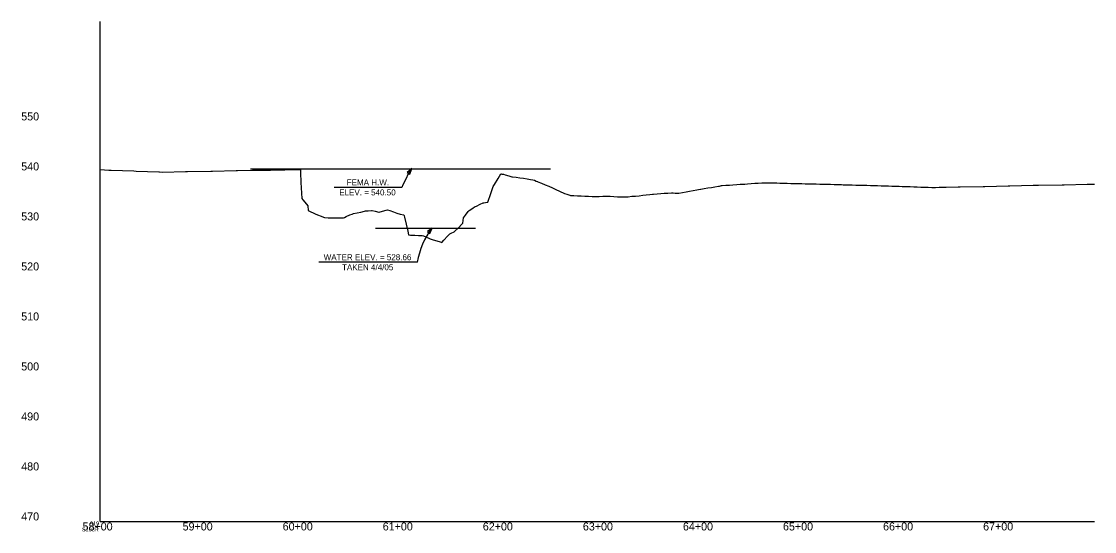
# Model space of a CAD drawing. Extents: x 1961504 to 1964196, y 1107046 to 1115093.
# Drawn here: x 1961505 to 1962577, y 1113082 to 1113593 of the extents above; entities that cross this region are included whole.
import ezdxf

# ---------------------------------------------------------------- set-up
doc = ezdxf.new("R2010")
doc.units = 0
for name, color, linetype in [('Level 40', 7, 'Continuous'), ('Level 41', 7, 'Continuous'), ('Level 42', 7, 'Continuous'), ('Level 63', 7, 'Continuous')]:
    doc.layers.add(name, color=color, linetype=linetype)

msp = doc.modelspace()

# ---------------------------------------------------------------- linework, layer by layer
at = {"layer": 'Level 40'}
for points in [[(1961583.7, 1113444.4), (1961592.3, 1113444), (1961594.7, 1113444), (1961617.3, 1113443.1), (1961619.7, 1113443), (1961642.3, 1113442.2), (1961642.8, 1113442.1), (1961645.9, 1113442), (1961668.8, 1113442.4), (1961670.9, 1113442.5), (1961694.1, 1113442.9), (1961695.9, 1113443), (1961719.5, 1113443.4), (1961720.9, 1113443.4), (1961735.7, 1113443.7), (1961739.3, 1113443.8), (1961742.9, 1113443.8), (1961744.8, 1113443.9), (1961745.9, 1113443.9), (1961745.9, 1113443.9), (1961746.5, 1113443.9), (1961748.4, 1113443.9), (1961749.5, 1113444), (1961750.2, 1113444), (1961753.8, 1113444), (1961757.4, 1113444.1), (1961761, 1113444.2), (1961764.6, 1113444.3), (1961768.2, 1113444.3), (1961771.8, 1113444.4), (1961773.4, 1113444.4), (1961774.2, 1113444.5), (1961775.4, 1113444.5), (1961779.1, 1113444.6), (1961782.7, 1113444.6), (1961783.7, 1113444.6), (1961783.8, 1113444.7), (1961783.9, 1113441.5), (1961784.2, 1113431.5), (1961785.3, 1113415.4), (1961786.3, 1113414.3), (1961789.9, 1113409.8), (1961791.2, 1113408.1), (1961791.5, 1113403.4), (1961793.5, 1113402.4), (1961797.1, 1113400.8), (1961798.5, 1113400.1), (1961800.7, 1113399.2), (1961804.3, 1113397.8), (1961806.9, 1113396.7), (1961807.9, 1113396.4), (1961808, 1113396.4), (1961811.6, 1113396.3), (1961815.2, 1113396.3), (1961818.8, 1113396.3), (1961822.4, 1113396.3), (1961826, 1113396.2), (1961826.8, 1113396.2), (1961827.9, 1113396.6), (1961829.6, 1113397.4), (1961833.2, 1113399.1), (1961835.4, 1113400), (1961836.8, 1113400.4), (1961840.4, 1113401.2), (1961844.1, 1113402), (1961847.7, 1113402.9), (1961848.7, 1113403.1), (1961851.3, 1113403.3), (1961854.9, 1113403.6), (1961855.4, 1113403.6), (1961858.5, 1113402.8), (1961862.1, 1113401.9), (1961862.3, 1113401.9), (1961865.7, 1113402.8), (1961869.3, 1113403.9), (1961870.6, 1113404.2), (1961873, 1113403.4), (1961876.6, 1113402.1), (1961880.2, 1113400.9), (1961883.4, 1113399.7), (1961883.8, 1113399.7), (1961886.7, 1113399.2), (1961887.3, 1113398.5), (1961887.4, 1113398.3), (1961887.8, 1113396.9), (1961891, 1113382.7), (1961891.8, 1113379.2), (1961893.7, 1113378.9), (1961894.6, 1113378.9), (1961898.2, 1113378.7), (1961901.8, 1113378.6), (1961905.5, 1113378.4), (1961906.8, 1113378.3), (1961909.1, 1113377.2), (1961912.7, 1113375.5), (1961913.4, 1113375.1), (1961916.3, 1113374.2), (1961919.9, 1113373.2), (1961923.5, 1113372.1), (1961925.1, 1113371.6), (1961927.1, 1113373.8)], [(1961927.1, 1113373.8), (1961930.7, 1113377.9), (1961932.9, 1113380.3), (1961934.3, 1113380.9), (1961937.5, 1113382.3), (1961938, 1113382.7), (1961941.6, 1113386.3), (1961945.2, 1113389.9), (1961946.1, 1113390.8), (1961946.8, 1113396.1), (1961948.8, 1113398.9), (1961951.3, 1113402.6), (1961952.4, 1113403.4), (1961956, 1113405.9), (1961957.8, 1113407.2), (1961959.6, 1113408), (1961963.2, 1113409.7), (1961966.4, 1113411.2), (1961966.9, 1113411.2), (1961967, 1113411.2), (1961970.5, 1113411.7), (1961971.1, 1113411.8), (1961974.1, 1113420.5), (1961976.5, 1113427.5), (1961977.7, 1113429.5), (1961981.3, 1113435.6), (1961984, 1113440.1), (1961984.3, 1113440.1), (1961984.9, 1113440), (1961986.7, 1113439.8), (1961988.5, 1113439.3), (1961992.1, 1113438.2), (1961995.1, 1113437.3), (1961995.7, 1113437.2), (1961999.4, 1113436.7), (1962003, 1113436.2), (1962006.6, 1113435.7), (1962010.2, 1113435.2), (1962013.8, 1113434.6), (1962016.1, 1113434.3), (1962017.4, 1113433.8), (1962017.4, 1113433.7), (1962017.5, 1113433.7), (1962019.3, 1113433), (1962020.7, 1113432.5), (1962021, 1113432.3), (1962024.6, 1113430.8), (1962028.2, 1113429.3), (1962031.9, 1113427.7), (1962035.5, 1113426.1), (1962039.1, 1113424.5), (1962042.7, 1113422.8), (1962044, 1113422.2), (1962046.3, 1113421.2), (1962047.8, 1113420.5), (1962049.9, 1113419.7), (1962053, 1113418.7), (1962053.5, 1113418.6), (1962057.1, 1113418.4), (1962060.7, 1113418.2), (1962060.7, 1113418.2), (1962064.4, 1113418.1), (1962068, 1113418), (1962068, 1113418), (1962071.6, 1113417.8), (1962075.2, 1113417.6), (1962078.8, 1113417.4), (1962078.9, 1113417.4), (1962082.4, 1113417.5), (1962086, 1113417.7), (1962089.6, 1113417.8), (1962093, 1113417.9), (1962093.3, 1113417.8), (1962096.9, 1113417.5), (1962100.5, 1113417.2), (1962100.6, 1113417.2), (1962104.1, 1113417.2), (1962107.7, 1113417.2), (1962110.5, 1113417.2), (1962111.3, 1113417.3), (1962114.9, 1113417.7), (1962118.5, 1113418), (1962122.1, 1113418.3), (1962122.3, 1113418.3), (1962125.8, 1113418.7), (1962129.4, 1113419.2), (1962133, 1113419.5), (1962135.5, 1113419.8), (1962136.6, 1113419.9), (1962140.2, 1113420.3), (1962143.8, 1113420.6), (1962143.8, 1113420.6), (1962147.4, 1113420.8), (1962151, 1113421), (1962154.6, 1113421.1), (1962156.2, 1113421.1), (1962158.3, 1113421), (1962161.6, 1113420.7), (1962161.9, 1113420.8), (1962165.5, 1113421.5), (1962169.1, 1113422.2)], [(1962169.1, 1113422.2), (1962172.7, 1113422.9), (1962176.3, 1113423.5), (1962179.9, 1113424.2), (1962181.5, 1113424.4), (1962183.5, 1113424.9), (1962184, 1113425), (1962187.2, 1113425.5), (1962190.8, 1113426.1), (1962194.4, 1113426.6), (1962198, 1113427.1), (1962201.6, 1113427.7), (1962202.6, 1113427.8), (1962204.4, 1113428.4), (1962205.2, 1113428.4), (1962208.8, 1113428.7), (1962212.4, 1113429), (1962216, 1113429.2), (1962219.7, 1113429.4), (1962223.3, 1113429.7), (1962226.9, 1113429.9), (1962227.7, 1113430), (1962230.5, 1113430.2), (1962234.1, 1113430.4), (1962237.7, 1113430.7), (1962241.3, 1113430.9), (1962244.9, 1113431.1), (1962245.7, 1113431.2), (1962248.5, 1113431.2), (1962251.5, 1113431.2), (1962252.2, 1113431.2), (1962252.9, 1113431.2), (1962253.1, 1113431.1), (1962255.8, 1113431.1), (1962256.6, 1113431.1), (1962259.4, 1113431.1), (1962259.9, 1113431.1), (1962263, 1113431), (1962266.6, 1113430.9), (1962270.2, 1113430.8), (1962273.8, 1113430.6), (1962277.4, 1113430.5), (1962281, 1113430.4), (1962281.7, 1113430.4), (1962284.7, 1113430.4), (1962288.3, 1113430.3), (1962291.9, 1113430.3), (1962291.9, 1113430.3), (1962295.5, 1113430.2), (1962299.1, 1113430.1), (1962302.7, 1113429.9), (1962306.3, 1113429.8), (1962306.7, 1113429.8), (1962308.5, 1113429.8), (1962309.9, 1113429.8), (1962310.1, 1113429.8), (1962313.6, 1113429.7), (1962317.2, 1113429.6), (1962320.8, 1113429.5), (1962324.4, 1113429.4), (1962326.1, 1113429.3), (1962328, 1113429.3), (1962331.6, 1113429.2), (1962335.2, 1113429.1), (1962335.2, 1113429.1), (1962338.8, 1113429), (1962342.4, 1113428.9), (1962346.1, 1113428.8), (1962349.7, 1113428.7), (1962353.3, 1113428.6), (1962354.7, 1113428.6), (1962356.9, 1113428.5), (1962360.2, 1113428.4), (1962360.5, 1113428.4), (1962364.1, 1113428.3), (1962367.7, 1113428.2), (1962371.3, 1113428.1), (1962374.9, 1113428), (1962378.6, 1113427.8), (1962381.8, 1113427.7), (1962382.2, 1113427.7), (1962385.2, 1113427.6), (1962385.8, 1113427.6), (1962389.4, 1113427.5), (1962393, 1113427.4), (1962396.6, 1113427.2), (1962400.2, 1113427.1), (1962403.8, 1113427), (1962407.5, 1113426.9), (1962407.7, 1113426.9), (1962410.2, 1113426.8), (1962410.6, 1113426.8), (1962411.1, 1113426.7), (1962414.7, 1113426.6), (1962416, 1113426.6), (1962418.3, 1113426.6), (1962418.4, 1113426.6), (1962421.9, 1113426.7), (1962425.5, 1113426.8), (1962429.1, 1113426.8), (1962441, 1113427.1)], [(1962441, 1113427.1), (1962443.1, 1113427.1), (1962466, 1113427.6), (1962467.8, 1113427.6), (1962491, 1113428.1), (1962492.6, 1113428.2), (1962516, 1113428.7), (1962516.2, 1113428.7), (1962520, 1113428.7), (1962521.3, 1113428.8), (1962545, 1113429.3), (1962547, 1113429.3), (1962570, 1113429.8), (1962572.6, 1113429.8), (1962577.3, 1113429.9)]]:
    msp.add_lwpolyline(points, dxfattribs=at)
at = {"layer": 'Level 41'}
for p, q in [((1961733.7, 1113445.1), (1962033.7, 1113445.1)), ((1961885.2, 1113426.6), (1961817.5, 1113426.6)), ((1961858.7, 1113385.9), (1961958.7, 1113385.9)), ((1961900.6, 1113351.8), (1961802, 1113351.8))]:
    msp.add_line(p, q, dxfattribs=at)
for points in [[(1961893.1, 1113439.8), (1961894.9, 1113445.6), (1961890.5, 1113441.5)], [(1961913.1, 1113380.5), (1961915.4, 1113386), (1961910.6, 1113382.4)]]:
    msp.add_lwpolyline(points, close=True, dxfattribs=at)
for centre, radius, start, end in [((1961987.7, 1113386.1), 110.2, 147.3254, 158.4252), ((1961975.9, 1113339.7), 76.3, 142.5817, 170.8964)]:
    msp.add_arc(centre, radius, start, end, dxfattribs=at)
at = {"layer": 'Level 63'}
for q in [(1961583.7, 1113592.6), (1962577.3, 1113092.6), (1961583.7, 1113092.6)]:
    msp.add_line((1961583.7, 1113092.6), q, dxfattribs=at)

# ---------------------------------------------------------------- texts
at = {"layer": 'Level 41'}
for s, p in [('FEMA H.W.', (1961830, 1113428.6)), ('ELEV. = 540.50', (1961822.5, 1113418.6)), ('WATER ELEV. = 528.66', (1961807, 1113353.8)), ('TAKEN 4/4/05', (1961825.3, 1113343.8))]:
    msp.add_text(s, height=6, dxfattribs=at).set_placement(p)
at = {"layer": 'Level 42'}
for s, p in [('550', (1961504.7, 1113493.6)), ('540', (1961504.7, 1113443.6)), ('530', (1961504.7, 1113393.6)), ('520', (1961504.7, 1113343.6)), ('510', (1961504.7, 1113293.6)), ('500', (1961504.7, 1113243.6)), ('490', (1961504.7, 1113193.6)), ('480', (1961504.7, 1113143.6)), ('470', (1961504.7, 1113093.6)), ('58+00', (1961566, 1113083.6)), ('59+00', (1961666, 1113083.6)), ('60+00', (1961766, 1113083.6)), ('61+00', (1961866, 1113083.6)), ('62+00', (1961966, 1113083.6)), ('63+00', (1962066, 1113083.6)), ('64+00', (1962166, 1113083.6)), ('65+00', (1962266, 1113083.6)), ('66+00', (1962366, 1113083.6)), ('67+00', (1962466, 1113083.6))]:
    msp.add_text(s, height=8, dxfattribs=at).set_placement(p)
at = {"layer": 'Level 63'}
for s, p in [('919', (1961573.4, 1113088.6)), ('S103R', (1961565.3, 1113082.6))]:
    msp.add_text(s, height=4, dxfattribs=at).set_placement(p)

doc.saveas('drawing.dxf')
